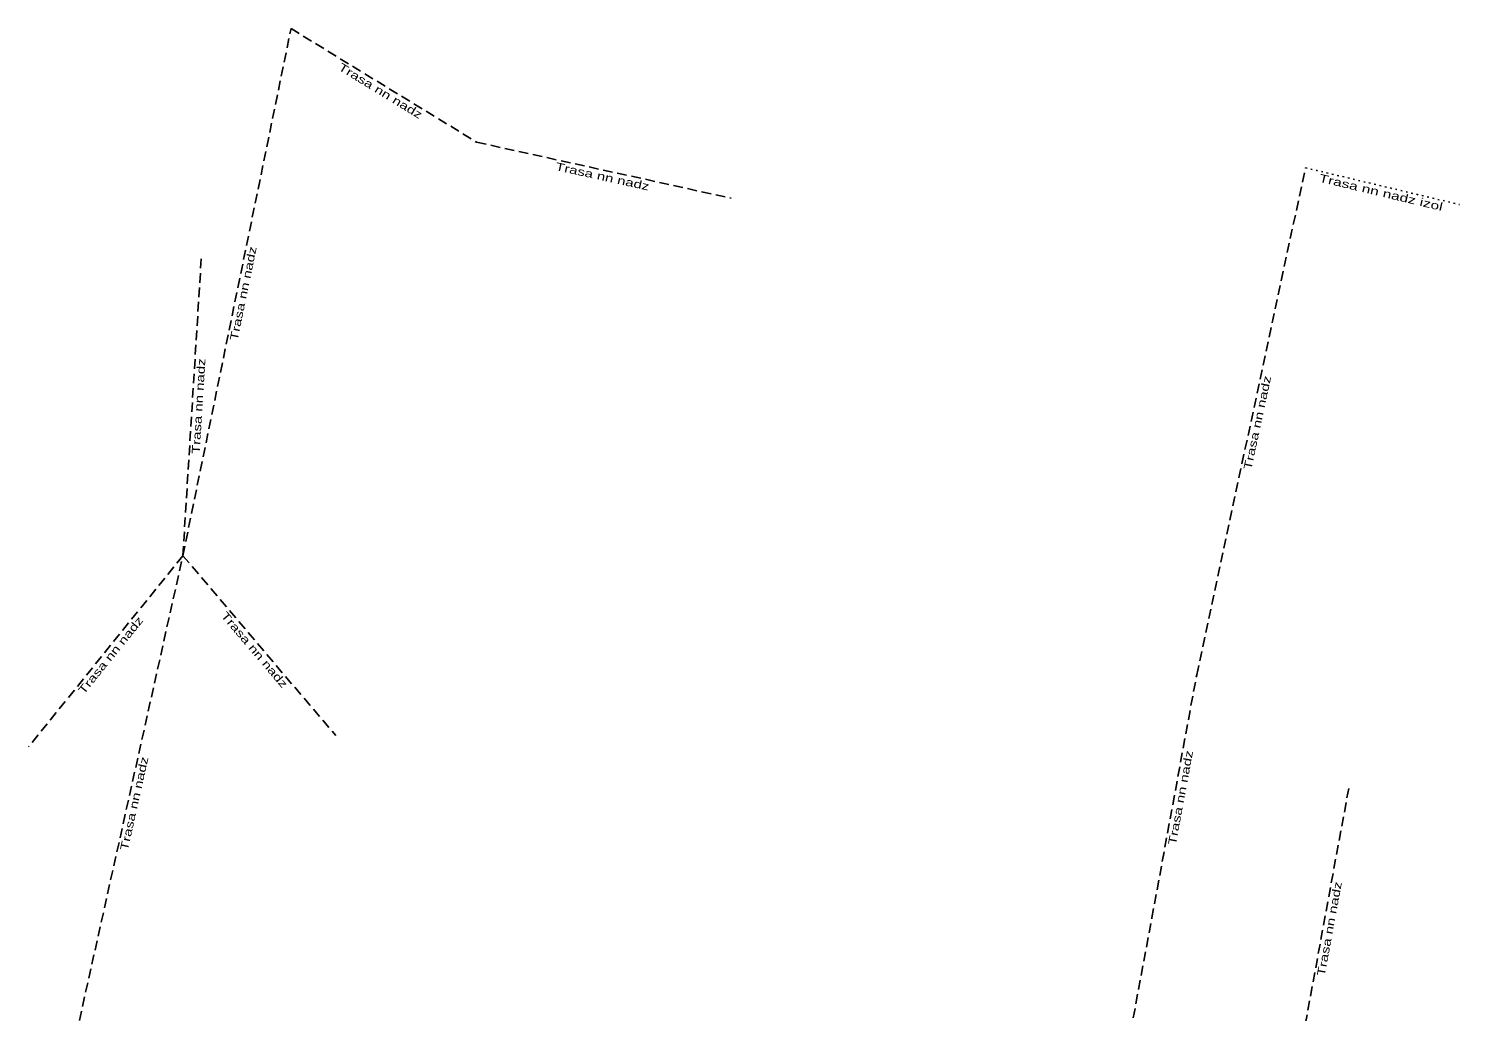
# Model space of a CAD drawing. Extents: x -733620 to -732615, y -1025255 to -1024617.
# Drawn here: x -733230.1 to -733140.7, y -1024812.8 to -1024751.4 of the extents above; entities that cross this region are included whole.
import ezdxf
from ezdxf.enums import TextEntityAlignment as Align

# ---------------------------------------------------------------- set-up
doc = ezdxf.new("R2010")
doc.units = 0
doc.header["$LTSCALE"] = 0.2
doc.linetypes.add('DOTTED', pattern=[1.5, 0.3, -1.2])
doc.linetypes.add('MEDIUM_DASHED', pattern=[4.5, 3, -1.5])
doc.layers.add('11', color=7, linetype='MEDIUM_DASHED', lineweight=25)
doc.layers.add('20', color=7, linetype='Continuous')

msp = doc.modelspace()

# ---------------------------------------------------------------- linework, layer by layer
at = {"layer": '11'}
for p, q in [((-733220.46, -1024784.35), (-733213.7, -1024751.4)), ((-733213.7, -1024751.4), (-733202.1, -1024758.5)), ((-733202.1, -1024758.5), (-733186.2, -1024762)), ((-733157.1, -1024791.8), (-733150.3, -1024760.1)), ((-733220.46, -1024784.35), (-733219.3, -1024765.6)), ((-733220.46, -1024784.35), (-733230.1, -1024796.3)), ((-733159.9, -1024807), (-733157.1, -1024791.8)), ((-733147.6, -1024798.9), (-733150.8, -1024816.3)), ((-733163.7, -1024827.4), (-733159.9, -1024807))]:
    msp.add_line(p, q, dxfattribs=at)
at = {"layer": '11', "linetype": 'DOTTED'}
msp.add_line((-733150.3, -1024760.1), (-733140.681, -1024762.397), dxfattribs=at)
at = {"layer": '11'}
msp.add_lwpolyline([(-733227.32, -1024815.16), (-733220.46, -1024784.35), (-733210.9, -1024795.6)], dxfattribs=at)

# ---------------------------------------------------------------- texts
at = {"layer": '20'}
for s, rotation, width, p in [('Trasa nn nadz', 328.53, 1.4, (-733208.239, -1024755.504)), ('Trasa nn nadz', 347.586, 1.4, (-733194.2892, -1024760.8847)), ('Trasa nn nadz izol', 346.571, 1.45, (-733145.6406, -1024761.88)), ('Trasa nn nadz', 78.406, 1.4, (-733216.4423, -1024768.0047)), ('Trasa nn nadz', 86.46, 1.4, (-733219.2309, -1024775.0149)), ('Trasa nn nadz', 77.893, 1.4, (-733153.0636, -1024776.0859)), ('Trasa nn nadz', 51.107, 1.4, (-733224.7744, -1024790.7325)), ('Trasa nn nadz', 310.357, 1.4, (-733216.1753, -1024790.3956)), ('Trasa nn nadz', 77.448, 1.4, (-733223.2559, -1024799.8958)), ('Trasa nn nadz', 79.563, 1.4, (-733157.8606, -1024799.5168)), ('Trasa nn nadz', 79.579, 1.4, (-733148.5605, -1024807.7167))]:
    msp.add_text(s, height=0.5, rotation=rotation, dxfattribs=dict(at, width=width)).set_placement(p, align=Align.CENTER)

doc.saveas('drawing.dxf')
